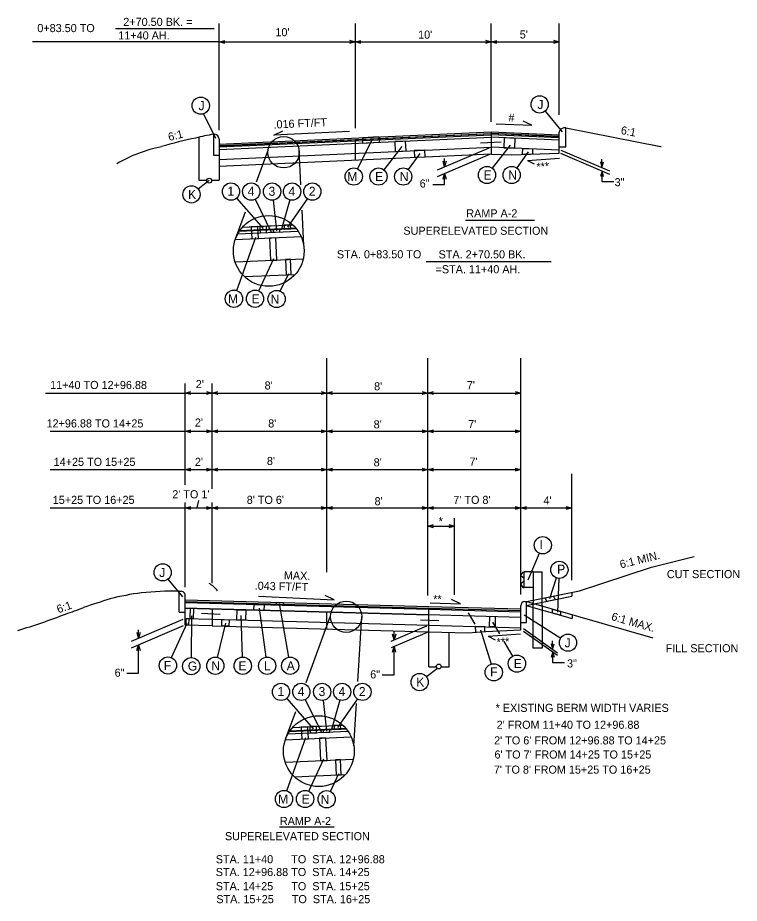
# Model space of a CAD drawing. Extents: x -196 to 300, y -73 to 205.
# Drawn here: x -141.1 to -87.5, y 20.9 to 86.5 of the extents above; entities that cross this region are included whole.
import ezdxf

# ---------------------------------------------------------------- set-up
doc = ezdxf.new("R2010")
doc.units = 0
for name, color, linetype in [('Level 4', 7, 'Continuous'), ('Level 59', 7, 'Continuous'), ('Level 6', 7, 'Continuous'), ('Level 60', 7, 'Continuous'), ('Level 7', 7, 'Continuous')]:
    doc.layers.add(name, color=color, linetype=linetype)

msp = doc.modelspace()

# ---------------------------------------------------------------- linework, layer by layer
at = {"layer": 'Level 4'}
for p, q in [((-126.112, 78.207), (-126.112, 86.108)), ((-116.034, 86.108), (-116.034, 78.358)), ((-105.955, 78.833), (-105.955, 86.108)), ((-100.894, 79.348), (-100.894, 86.108)), ((-133.819, 85.738), (-126.488, 85.738)), ((-126.112, 84.751), (-139.958, 84.751)), ((-126.112, 84.751), (-116.034, 84.751)), ((-116.034, 84.751), (-105.955, 84.751)), ((-105.955, 84.751), (-100.894, 84.751)), ((-100.894, 79.348), (-100.894, 82.935)), ((-102.941, 78.567), (-103.573, 78.871)), ((-122.066, 77.842), (-121.401, 78.162)), ((-105.574, 78.685), (-102.941, 78.567)), ((-116.44, 78.095), (-122.066, 77.842)), ((-106.113, 76.876), (-109.949, 75.244)), ((-106.081, 76.392), (-109.949, 74.747)), ((-100.81, 76.501), (-97.165, 74.95)), ((-100.779, 76.729), (-97.175, 75.196)), ((-109.395, 75.48), (-109.395, 76.109)), ((-103.262, 75.961), (-100.869, 76.132)), ((-103.262, 75.961), (-102.748, 75.697)), ((-97.729, 75.432), (-97.729, 76.061)), ((-109.395, 74.168), (-109.395, 74.983)), ((-97.719, 74.371), (-97.719, 75.186)), ((-96.843, 74.371), (-97.719, 74.371)), ((-110.271, 74.168), (-109.395, 74.168)), ((-107.851, 71.528), (-102.742, 71.528)), ((-110.767, 68.456), (-101.497, 68.456)), ((-118.14, 45.432), (-118.14, 61.29)), ((-110.653, 43.699), (-110.653, 61.29)), ((-103.742, 43.772), (-103.742, 61.29)), ((-128.64, 51.908), (-128.64, 59.432)), ((-126.64, 51.621), (-126.64, 59.432)), ((-138.987, 58.714), (-128.64, 58.714)), ((-128.64, 58.714), (-126.64, 58.714)), ((-126.64, 58.714), (-118.14, 58.714)), ((-118.287, 58.732), (-117.87, 58.732)), ((-118.14, 58.714), (-110.653, 58.714)), ((-110.653, 58.714), (-103.742, 58.714)), ((-138.655, 55.875), (-128.64, 55.875)), ((-128.64, 55.875), (-126.64, 55.875)), ((-126.64, 55.875), (-118.14, 55.875)), ((-118.287, 55.893), (-117.87, 55.893)), ((-118.14, 55.875), (-110.653, 55.875)), ((-110.653, 55.875), (-103.742, 55.875)), ((-138.655, 53.036), (-128.64, 53.036)), ((-128.64, 53.036), (-126.64, 53.036)), ((-126.64, 53.036), (-118.14, 53.036)), ((-126.64, 52.276), (-126.64, 52.666)), ((-118.287, 53.054), (-117.87, 53.054)), ((-118.14, 53.036), (-110.653, 53.036)), ((-110.653, 53.036), (-103.742, 53.036)), ((-99.953, 44.849), (-99.953, 52.717)), ((-128.64, 44.328), (-128.64, 50.586)), ((-127.652, 50.751), (-127.765, 50.203)), ((-126.64, 44.623), (-126.64, 50.608)), ((-138.655, 50.197), (-128.64, 50.197)), ((-128.64, 50.197), (-126.64, 50.197)), ((-126.64, 50.197), (-118.14, 50.197)), ((-118.287, 50.215), (-117.87, 50.215)), ((-118.14, 50.197), (-110.653, 50.197)), ((-110.653, 50.197), (-99.953, 50.197)), ((-108.653, 43.746), (-108.653, 49.443)), ((-110.653, 48.843), (-108.653, 48.843)), ((-123.205, 43.645), (-117.58, 43.392)), ((-117.58, 43.392), (-118.245, 43.712)), ((-108.215, 43.079), (-108.88, 43.399)), ((-110.473, 43.163), (-108.215, 43.079)), ((-128.817, 41.933), (-132.653, 40.301)), ((-128.785, 41.449), (-132.653, 39.804)), ((-110.735, 41.436), (-113.398, 40.303)), ((-132.099, 40.537), (-132.099, 41.166)), ((-110.703, 40.952), (-113.373, 39.816)), ((-113.142, 40.412), (-113.142, 41.041)), ((-106.166, 40.686), (-103.772, 40.857)), ((-103.552, 41.243), (-101.03, 39.456)), ((-103.551, 41.06), (-101.021, 39.268)), ((-106.166, 40.686), (-105.651, 40.422)), ((-101.385, 39.706), (-101.385, 40.335)), ((-132.099, 37.94), (-132.099, 40.04)), ((-113.142, 37.815), (-113.142, 39.914)), ((-101.375, 38.706), (-101.375, 39.521)), ((-100.499, 38.706), (-101.375, 38.706)), ((-132.975, 37.94), (-132.099, 37.94)), ((-114.018, 37.815), (-113.142, 37.815)), ((-121.647, 26.54), (-117.592, 26.54))]:
    msp.add_line(p, q, dxfattribs=at)
for points in [[(-125.692, 84.635), (-126.112, 84.751), (-125.692, 84.863)], [(-116.454, 84.867), (-116.034, 84.751), (-116.454, 84.639)], [(-115.614, 84.635), (-116.034, 84.751), (-115.614, 84.863)], [(-106.375, 84.867), (-105.955, 84.751), (-106.375, 84.639)], [(-105.535, 84.635), (-105.955, 84.751), (-105.535, 84.863)], [(-101.314, 84.867), (-100.894, 84.751), (-101.314, 84.639)], [(-109.279, 75.9), (-109.395, 75.48), (-109.507, 75.9)], [(-97.845, 75.852), (-97.729, 75.432), (-97.617, 75.852)], [(-109.511, 74.563), (-109.395, 74.983), (-109.283, 74.563)], [(-97.603, 74.766), (-97.719, 75.186), (-97.831, 74.766)], [(-128.22, 58.598), (-128.64, 58.714), (-128.22, 58.826)], [(-127.06, 58.83), (-126.64, 58.714), (-127.06, 58.602)], [(-126.22, 58.598), (-126.64, 58.714), (-126.22, 58.826)], [(-118.56, 58.83), (-118.14, 58.714), (-118.56, 58.602)], [(-117.72, 58.598), (-118.14, 58.714), (-117.72, 58.826)], [(-111.073, 58.83), (-110.653, 58.714), (-111.073, 58.602)], [(-110.233, 58.598), (-110.653, 58.714), (-110.233, 58.826)], [(-104.162, 58.83), (-103.742, 58.714), (-104.162, 58.602)], [(-128.22, 55.759), (-128.64, 55.875), (-128.22, 55.987)], [(-127.06, 55.991), (-126.64, 55.875), (-127.06, 55.763)], [(-126.22, 55.759), (-126.64, 55.875), (-126.22, 55.987)], [(-118.56, 55.991), (-118.14, 55.875), (-118.56, 55.763)], [(-117.72, 55.759), (-118.14, 55.875), (-117.72, 55.987)], [(-111.073, 55.991), (-110.653, 55.875), (-111.073, 55.763)], [(-110.233, 55.759), (-110.653, 55.875), (-110.233, 55.987)], [(-104.162, 55.991), (-103.742, 55.875), (-104.162, 55.763)], [(-128.22, 52.92), (-128.64, 53.036), (-128.22, 53.148)], [(-127.06, 53.152), (-126.64, 53.036), (-127.06, 52.924)], [(-126.22, 52.92), (-126.64, 53.036), (-126.22, 53.148)], [(-118.56, 53.152), (-118.14, 53.036), (-118.56, 52.924)], [(-117.72, 52.92), (-118.14, 53.036), (-117.72, 53.148)], [(-111.073, 53.152), (-110.653, 53.036), (-111.073, 52.924)], [(-110.233, 52.92), (-110.653, 53.036), (-110.233, 53.148)], [(-104.162, 53.152), (-103.742, 53.036), (-104.162, 52.924)], [(-128.22, 50.081), (-128.64, 50.197), (-128.22, 50.309)], [(-127.06, 50.313), (-126.64, 50.197), (-127.06, 50.085)], [(-126.22, 50.081), (-126.64, 50.197), (-126.22, 50.309)], [(-118.56, 50.313), (-118.14, 50.197), (-118.56, 50.085)], [(-117.72, 50.081), (-118.14, 50.197), (-117.72, 50.309)], [(-111.073, 50.313), (-110.653, 50.197), (-111.073, 50.085)], [(-110.233, 50.081), (-110.653, 50.197), (-110.233, 50.309)], [(-104.162, 50.313), (-103.742, 50.197), (-104.162, 50.085)], [(-103.322, 50.081), (-103.742, 50.197), (-103.322, 50.309)], [(-100.373, 50.313), (-99.953, 50.197), (-100.373, 50.085)], [(-110.233, 48.727), (-110.653, 48.843), (-110.233, 48.955)], [(-109.073, 48.959), (-108.653, 48.843), (-109.073, 48.731)], [(-131.983, 40.957), (-132.099, 40.537), (-132.211, 40.957)], [(-113.026, 40.832), (-113.142, 40.412), (-113.254, 40.832)], [(-101.501, 40.126), (-101.385, 39.706), (-101.273, 40.126)], [(-132.215, 39.62), (-132.099, 40.04), (-131.987, 39.62)], [(-113.258, 39.494), (-113.142, 39.914), (-113.03, 39.494)], [(-101.259, 39.101), (-101.375, 39.521), (-101.487, 39.101)]]:
    msp.add_lwpolyline(points, dxfattribs=at)
for points in [[(-101.94, 43.53), (-101.327, 43.65), (-101.198, 43.389), (-101.811, 43.269)], [(-101.393, 42.695), (-100.793, 42.525), (-100.796, 42.234), (-101.396, 42.404)]]:
    msp.add_lwpolyline(points, close=True, dxfattribs=at)
at = {"layer": 'Level 59'}
for p, q in [((-101.943, 79.622), (-100.671, 78.09)), ((-127.282, 79.416), (-126.394, 77.617)), ((-114.823, 77.443), (-115.854, 75.339)), ((-112.58, 76.982), (-113.91, 75.269)), ((-104.534, 77.098), (-105.865, 75.385)), ((-111.238, 76.475), (-112.096, 75.283)), ((-103.192, 76.591), (-104.05, 75.399)), ((-126.862, 74.46), (-127.668, 73.834)), ((-124.824, 73.168), (-122.863, 70.906)), ((-123.455, 73.078), (-122.25, 70.638)), ((-122.121, 73.016), (-121.861, 70.752)), ((-120.885, 73.036), (-121.503, 70.86)), ((-119.572, 73.126), (-121.047, 71.014)), ((-124.81, 66.307), (-123.406, 70.269)), ((-123.187, 66.284), (-122.063, 68.69)), ((-121.583, 66.264), (-120.951, 67.586)), ((-103.195, 44.86), (-102.363, 46.839)), ((-128.814, 43.595), (-129.904, 44.923)), ((-101.606, 43.475), (-101.09, 45.001)), ((-100.999, 42.472), (-100.909, 44.967)), ((-122.643, 39.128), (-123.115, 42.761)), ((-120.96, 39.124), (-121.633, 43.098)), ((-128.18, 39.1), (-128.139, 42.193)), ((-124.389, 39.133), (-124.476, 42.223)), ((-103.492, 42.276), (-100.788, 40.543)), ((-129.655, 39.095), (-128.502, 41.65)), ((-126.251, 39.114), (-125.622, 41.65)), ((-105.847, 41.727), (-105.329, 40.848)), ((-106.726, 41.164), (-105.941, 38.618)), ((-104.995, 40.28), (-104.359, 39.2)), ((-109.937, 38.301), (-110.743, 37.675)), ((-121.111, 36.074), (-119.151, 33.813)), ((-119.743, 35.984), (-118.538, 33.545)), ((-118.408, 35.922), (-118.148, 33.658)), ((-117.173, 35.943), (-117.791, 33.767)), ((-115.86, 36.033), (-117.334, 33.921)), ((-121.098, 29.214), (-119.694, 33.176)), ((-119.475, 29.191), (-118.351, 31.597)), ((-117.871, 29.17), (-117.239, 30.493))]:
    msp.add_line(p, q, dxfattribs=at)
for points in [[(-115.482, 77.25), (-114.239, 77.305), (-114.257, 77.701), (-115.5, 77.645)], [(-105.006, 76.9), (-104.193, 76.864), (-104.16, 77.597), (-104.973, 77.633)], [(-113.066, 76.624), (-112.257, 76.66), (-112.29, 77.393), (-113.099, 77.357)], [(-103.62, 76.393), (-103.606, 76.838), (-102.874, 76.811), (-102.874, 76.811), (-102.879, 76.42)], [(-111.63, 76.191), (-110.834, 76.227), (-110.856, 76.723), (-111.652, 76.687)], [(-123.698, 70.146), (-123.213, 70.166), (-123.26, 71.063), (-123.745, 71.042)], [(-123.084, 70.601), (-122.6, 70.622), (-122.62, 71.092), (-123.105, 71.071)], [(-121.295, 70.87), (-120.81, 70.89), (-120.824, 71.172), (-121.309, 71.152)], [(-122.107, 70.645), (-121.622, 70.666), (-121.631, 70.853), (-122.116, 70.833)], [(-122.315, 68.553), (-121.83, 68.573), (-121.908, 70.229), (-122.392, 70.208)], [(-121.157, 67.481), (-120.779, 67.497), (-120.827, 68.627), (-121.205, 68.611)], [(-128.263, 41.989), (-128.242, 42.751), (-128.03, 42.745), (-128.051, 41.983)], [(-128.57, 41.512), (-128.557, 41.997), (-128.376, 41.992), (-128.389, 41.507)], [(-119.986, 33.053), (-119.501, 33.073), (-119.548, 33.97), (-120.033, 33.949)], [(-119.372, 33.508), (-118.888, 33.529), (-118.908, 33.999), (-119.393, 33.978)], [(-118.395, 33.552), (-117.91, 33.573), (-117.919, 33.76), (-118.404, 33.74)], [(-117.583, 33.776), (-117.098, 33.797), (-117.112, 34.079), (-117.596, 34.059)], [(-118.603, 31.46), (-118.118, 31.48), (-118.196, 33.136), (-118.68, 33.115)], [(-117.445, 30.388), (-117.067, 30.404), (-117.115, 31.534), (-117.493, 31.518)]]:
    msp.add_lwpolyline(points, close=True, dxfattribs=at)
for centre in [(-127.484, 80.022), (-102.351, 80.114), (-106.257, 74.881), (-104.424, 74.881), (-116.136, 74.765), (-114.302, 74.765), (-112.469, 74.765), (-125.242, 73.65), (-123.738, 73.65), (-122.193, 73.65), (-120.71, 73.65), (-119.207, 73.65), (-128.172, 73.442), (-125.023, 65.705), (-123.458, 65.705), (-121.858, 65.687), (-102.115, 47.428), (-130.309, 45.417), (-100.886, 45.606), (-100.246, 40.205), (-129.918, 38.513), (-128.189, 38.461), (-126.405, 38.494), (-124.371, 38.494), (-122.561, 38.494), (-120.853, 38.494), (-104.035, 38.65), (-105.753, 38.007), (-111.248, 37.283), (-121.53, 36.557), (-120.026, 36.557), (-118.481, 36.557), (-116.998, 36.557), (-115.494, 36.557), (-121.311, 28.612), (-119.746, 28.612), (-118.146, 28.594)]:
    msp.add_circle(centre, 0.639, dxfattribs=at)
at = {"layer": 'Level 6'}
for p, q in [((-100.396, 78.37), (-100.556, 78.37)), ((-100.396, 78.37), (-93.379, 77.003)), ((-100.396, 76.964), (-100.396, 78.37)), ((-127.617, 77.681), (-127.617, 74.486)), ((-126.536, 77.902), (-126.536, 76.347)), ((-126.536, 77.902), (-126.444, 77.902)), ((-126.112, 77.169), (-105.955, 78.074)), ((-126.112, 77.064), (-105.955, 77.969)), ((-126.112, 76.772), (-105.955, 77.677)), ((-126.112, 77.539), (-126.112, 74.486)), ((-105.955, 78.074), (-105.955, 76.446)), ((-100.896, 77.742), (-105.955, 77.969)), ((-100.908, 77.451), (-105.955, 77.677)), ((-100.896, 76.491), (-100.896, 78.054)), ((-126.112, 76.038), (-105.955, 76.943)), ((-116.034, 77.465), (-116.034, 75.993)), ((-106.746, 77.274), (-105.204, 77.336)), ((-100.896, 76.716), (-105.957, 76.943)), ((-100.896, 76.964), (-100.396, 76.964)), ((-94.261, 77.157), (-93.343, 76.983)), ((-126.536, 76.347), (-126.112, 76.347)), ((-126.112, 75.541), (-105.955, 76.446)), ((-105.957, 76.436), (-104.428, 76.364)), ((-104.428, 76.364), (-100.896, 76.491)), ((-127.617, 74.486), (-127.042, 74.486)), ((-126.681, 74.486), (-126.112, 74.486)), ((-124.579, 70.769), (-120.445, 70.955)), ((-124.382, 71.014), (-121.919, 71.124)), ((-124.924, 70.094), (-120.041, 70.313)), ((-124.933, 68.435), (-119.883, 68.661)), ((-124.239, 67.342), (-120.476, 67.511)), ((-94.065, 45.808), (-90.899, 46.585)), ((-103.73, 45.233), (-103.582, 45.438)), ((-103.582, 45.438), (-103.494, 45.453)), ((-102.828, 45.453), (-103.494, 45.453)), ((-103.494, 44.286), (-103.494, 45.453)), ((-102.828, 45.453), (-102.828, 43.203)), ((-102.828, 45.453), (-102.161, 45.453)), ((-102.161, 42.95), (-102.161, 45.453)), ((-99.387, 44.051), (-94.065, 45.808)), ((-103.525, 44.978), (-103.714, 45.126)), ((-103.714, 44.614), (-103.525, 44.761)), ((-129.089, 42.454), (-129.089, 44.022)), ((-129.089, 44.022), (-128.905, 44.022)), ((-103.582, 44.302), (-103.73, 44.506)), ((-103.582, 44.302), (-103.494, 44.286)), ((-102.828, 44.286), (-103.494, 44.286)), ((-103.331, 43.25), (-99.387, 44.051)), ((-128.64, 41.514), (-128.64, 43.622)), ((-103.355, 42.96), (-99.953, 43.65)), ((-99.953, 43.936), (-99.953, 43.65)), ((-128.64, 43.183), (-110.579, 42.687)), ((-128.64, 42.781), (-110.62, 42.286)), ((-128.64, 42.762), (-110.579, 42.265)), ((-126.64, 42.726), (-126.64, 41.459)), ((-110.579, 42.687), (-103.742, 42.499)), ((-110.579, 41.017), (-110.579, 42.685)), ((-103.742, 41.168), (-103.742, 42.958)), ((-103.46, 43.25), (-103.331, 43.25)), ((-103.355, 42.96), (-99.944, 41.999)), ((-103.331, 41.691), (-103.331, 43.25)), ((-103.331, 43.25), (-93.962, 40.573)), ((-102.828, 39.786), (-102.828, 43.203)), ((-102.161, 42.95), (-102.161, 39.786)), ((-129.089, 42.454), (-128.64, 42.454)), ((-127.42, 42.394), (-126.043, 42.33)), ((-118.14, 41.225), (-118.14, 42.473)), ((-110.62, 42.286), (-103.742, 42.097)), ((-99.944, 42.291), (-99.944, 41.999)), ((-128.64, 42), (-126.64, 41.945)), ((-126.64, 41.459), (-128.64, 41.514)), ((-126.64, 41.945), (-110.579, 41.503)), ((-126.64, 41.459), (-110.579, 41.017)), ((-111.197, 41.909), (-109.82, 41.845)), ((-110.579, 41.503), (-103.742, 41.315)), ((-103.742, 41.691), (-103.331, 41.691)), ((-110.579, 41.017), (-107.687, 40.938)), ((-110.579, 38.411), (-110.579, 41.017)), ((-109.069, 38.411), (-109.069, 40.974)), ((-107.687, 40.938), (-106.342, 41.033)), ((-106.342, 41.033), (-103.742, 41.168)), ((-102.161, 39.786), (-102.828, 39.786)), ((-110.579, 38.411), (-110.015, 38.411)), ((-109.656, 38.411), (-109.069, 38.411)), ((-120.867, 33.676), (-116.733, 33.862)), ((-120.67, 33.921), (-118.207, 34.031)), ((-121.212, 33.001), (-116.329, 33.22)), ((-121.221, 31.341), (-116.171, 31.568)), ((-120.527, 30.249), (-116.764, 30.418))]:
    msp.add_line(p, q, dxfattribs=at)
for centre, radius in [((-126.862, 74.46), 0.183), ((-109.835, 38.438), 0.18)]:
    msp.add_circle(centre, radius, dxfattribs=at)
for centre, radius, start, end in [((-100.515, 77.985), 0.387, 96.02749, 169.67861), ((-121.977, 48.662), 29.551, 101.48467, 106.57547), ((-123.373, 59.675), 18.499, 99.84483, 104.04247), ((-126.511, 77.507), 0.4, 4.50116, 80.36352), ((-128.259, 66.417), 10.774, 101.49358, 120.31113), ((-103.666, 45.188), 0.0781, 144.08393, 232.1285), ((-103.573, 44.823), 0.0781, 307.8715, 360), ((-129.358, 17.974), 26.049, 89.40827, 95.57705), ((-128.998, 43.673), 0.361, 351.83326, 75.13882), ((-103.666, 44.552), 0.0781, 127.8715, 215.91607), ((-117.132, -13.324), 59.281, 106.72669, 108.74418), ((-129.718, 26.712), 17.325, 97.20085, 104.96984), ((-146.38, 68.444), 27.585, 288.76299, 291.69708), ((-103.454, 42.963), 0.287, 91.07893, 181.04781), ((-154.192, 85.501), 46.288, 286.48159, 291.12853)]:
    msp.add_arc(centre, radius, start, end, dxfattribs=at)
at = {"layer": 'Level 60'}
for points in [[(-123.544, 42.613), (-123.531, 43.043), (-122.785, 43.022), (-122.798, 42.592)], [(-121.881, 43.007), (-121.876, 43.213), (-121.339, 43.18), (-121.344, 42.974)], [(-124.816, 41.886), (-124.795, 42.647), (-124.134, 42.629), (-124.155, 41.867)], [(-106.068, 41.379), (-106.046, 42.16), (-105.638, 42.149), (-105.66, 41.368)], [(-125.927, 41.43), (-125.913, 41.916), (-125.387, 41.901), (-125.4, 41.416)], [(-107.119, 40.978), (-106.414, 41.028), (-106.414, 41.388), (-107.144, 41.409)]]:
    msp.add_lwpolyline(points, close=True, dxfattribs=at)
at = {"layer": 'Level 7'}
for p, q in [((-126.112, 77.168), (-105.955, 78.073)), ((-126.112, 77.043), (-105.955, 77.948)), ((-126.112, 76.96), (-105.955, 77.865)), ((-105.955, 78.074), (-100.896, 77.846)), ((-100.896, 77.721), (-105.955, 77.948)), ((-100.896, 77.638), (-105.955, 77.865)), ((-123.357, 74.362), (-122.488, 76.73)), ((-120.064, 74.149), (-120.187, 76.712)), ((-119.847, 69.649), (-119.973, 72.268)), ((-124.908, 70.139), (-124.174, 72.139)), ((-124.383, 71.013), (-120.662, 71.18)), ((-124.732, 70.527), (-120.271, 70.727)), ((-124.613, 70.72), (-120.407, 70.909)), ((-128.64, 43.389), (-110.579, 42.893)), ((-128.646, 43.181), (-110.585, 42.685)), ((-128.644, 43.264), (-110.579, 42.768)), ((-110.585, 42.685), (-103.747, 42.497)), ((-110.579, 42.893), (-103.742, 42.705)), ((-110.579, 42.768), (-103.742, 42.58)), ((-119.659, 37.258), (-117.856, 42.197)), ((-115.838, 37.319), (-115.536, 42.157)), ((-107.657, 42.422), (-107.161, 41.566)), ((-116.135, 32.555), (-115.939, 35.696)), ((-121.196, 33.046), (-120.443, 35.11)), ((-121.019, 33.434), (-116.559, 33.634)), ((-120.901, 33.627), (-116.695, 33.816)), ((-120.67, 33.92), (-116.95, 34.087))]:
    msp.add_line(p, q, dxfattribs=at)
for centre, radius in [((-121.339, 76.564), 1.161), ((-122.44, 69.251), 2.623), ((-116.697, 42.13), 1.161), ((-118.728, 32.158), 2.623)]:
    msp.add_circle(centre, radius, dxfattribs=at)
msp.add_arc((-127.79, 42.881), 1.947, 36.81944, 61.15971, dxfattribs=at)

# ---------------------------------------------------------------- texts
at = {"layer": 'Level 4'}
for s, p in [('0+83.50 TO', (-139.606, 85.475)), ('2+70.50 BK. =', (-133.23, 85.933)), ('11+40 AH.', (-133.6, 84.928)), ("10'", (-121.946, 85.169)), ("10'", (-111.363, 84.989)), ("5'", (-103.827, 85.003)), ('#', (-104.661, 78.84)), ('6"', (-111.247, 73.951)), ('3"', (-96.79, 74.046)), ('RAMP A-2', (-107.792, 71.736)), ('SUPERELEVATED SECTION', (-112.457, 70.448)), ('STA. 0+83.50 TO', (-117.389, 68.701)), ('STA. 2+70.50 BK. ', (-109.845, 68.696)), ('=STA. 11+40 AH.', (-110.07, 67.592)), ('11+40 TO 12+96.88', (-138.655, 59.011)), ("2'", (-127.851, 59.077)), ("8'", (-122.747, 58.978)), ("8'", (-114.627, 58.912)), ("7'", (-107.75, 58.994)), ('12+96.88 TO 14+25', (-138.921, 56.161)), ("2'", (-127.917, 56.227)), ("8'", (-122.482, 56.161)), ("8'", (-114.66, 56.094)), ("7'", (-107.65, 56.111)), ('14+25 TO 15+25', (-138.393, 53.31)), ("2'", (-127.917, 53.31)), ("8'", (-122.578, 53.377)), ("8'", (-114.66, 53.277)), ("7'", (-107.551, 53.327)), ("2' TO 1'", (-129.597, 50.907)), ('15+25 TO 16+25', (-138.459, 50.493)), ("8' TO 6'", (-124.073, 50.493)), ("8'", (-114.594, 50.394)), ("7' TO 8'", (-108.753, 50.491)), ("4'", (-102.064, 50.455)), ('*', (-109.839, 48.91)), ('CUT SECTION', (-92.916, 44.989)), ('**', (-110.243, 43.135)), ('FILL SECTION', (-93.006, 39.491)), ('3"', (-100.318, 38.367)), ('6"', (-133.873, 37.68)), ('6"', (-114.917, 37.554)), ('* EXISTING BERM WIDTH VARIES', (-105.614, 35.072)), ("2' FROM 11+40 TO 12+96.88", (-105.539, 33.818)), ("2' TO 6' FROM 12+96.88 TO 14+25", (-105.724, 32.659)), ("6' TO 7' FROM 14+25 TO 15+25", (-105.699, 31.612)), ("7' TO 8' FROM 15+25 TO 16+25", (-105.748, 30.492)), ('RAMP A-2', (-121.614, 26.684)), ('SUPERELEVATED SECTION', (-125.688, 25.557)), ('STA. 11+40      TO  STA. 12+96.88', (-126.371, 23.847)), ('STA. 12+96.88 TO  STA. 14+25', (-126.375, 22.9)), ('STA. 14+25      TO  STA. 15+25', (-126.369, 21.851)), ('STA. 15+25      TO  STA. 16+25', (-126.328, 20.889))]:
    msp.add_text(s, height=0.6, dxfattribs=at).set_placement(p)
for s, rotation, p in [('.016 FT/FT', 2.57074, (-122.075, 78.32)), ('6:1', 13.91866, (-129.826, 77.394)), ('6:1', 348.97963, (-96.362, 77.932)), ('***', 4.07739, (-102.562, 75.188)), ('6:1 MIN.', 13.79506, (-96.328, 45.703)), ('MAX.', 358.42591, (-121.326, 44.907)), ('.043 FT/FT', 358.42591, (-123.489, 44.135)), ('6:1', 19.53014, (-138.041, 42.374)), ('6:1 MAX.', 344.04801, (-97.077, 41.892)), ('***', 4.07739, (-105.506, 39.935))]:
    msp.add_text(s, height=0.6, rotation=rotation, dxfattribs=at).set_placement(p)
at = {"layer": 'Level 59'}
for s, p in [('J', (-127.649, 79.686)), ('J', (-102.516, 79.777)), ('M', (-116.618, 74.428)), ('E', (-114.556, 74.428)), ('N', (-112.722, 74.428)), ('E', (-106.51, 74.544)), ('N', (-104.677, 74.544)), ('K', (-128.426, 73.106)), ('1', (-125.506, 73.338)), ('4', (-124.002, 73.338)), ('3', (-122.457, 73.338)), ('4', (-120.974, 73.338)), ('2', (-119.47, 73.338)), ('M', (-125.459, 65.366)), ('E', (-123.717, 65.366)), ('N', (-122.308, 65.335)), ('I', (-102.358, 47.139)), ('P', (-101.051, 45.317)), ('J', (-130.56, 45.07)), ('J', (-100.496, 39.857)), ('F', (-130.223, 38.181)), ('G', (-128.444, 38.136)), ('N', (-126.701, 38.155)), ('E', (-124.685, 38.155)), ('L', (-122.804, 38.155)), ('A', (-121.109, 38.155)), ('E', (-104.264, 38.321)), ('F', (-106.02, 37.702)), ('K', (-111.501, 36.947)), ('1', (-121.794, 36.245)), ('4', (-120.29, 36.245)), ('3', (-118.745, 36.245)), ('4', (-117.262, 36.245)), ('2', (-115.758, 36.245)), ('M', (-121.747, 28.273)), ('E', (-120.005, 28.273)), ('N', (-118.595, 28.242))]:
    msp.add_text(s, height=0.67, dxfattribs=at).set_placement(p)

doc.saveas('drawing.dxf')
